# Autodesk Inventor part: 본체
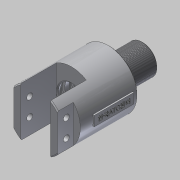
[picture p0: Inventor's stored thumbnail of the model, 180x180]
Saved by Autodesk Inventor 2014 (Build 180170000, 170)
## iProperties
Created: 2019-02
Part Number: 본체
Material: 알루미늄 6061
Document SubType Name: Modeling
Designer: 603-14
Density: 2.71 g/cm^3
Appearance: 알루미늄 - 평지
Mass: 336.883 g
Surface Area: 292.132 cm^2
Volume: 124.311 cm^3
Author: 603-14
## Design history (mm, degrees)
sketch "스케치1"
  geometry: L1 (-36, 0)-(36, 0); L2 (-36, 14)-(-36, 29); L3 (-36, 29)-(2, 29); L4 (2, 29)-(2, 13); L5 (2, 13)-(7, 13); L6 (7, 13)-(7, 15); L7 (7, 15)-(36, 15); L8 (36, 15)-(36, 7); L9 (-36, 14)-(-33.35, 14); L10 (-33.35, 14)-(-33.35, 16.2); L11 (-32.55, 17)-(-29.45, 17); L12 (-28.65, 16.2)-(-28.65, 14); L13 (-28.65, 14)-(-24.35, 14); L14 (-24.35, 14)-(-24.35, 16.2); L15 (-23.55, 17)-(-20.45, 17); L16 (-19.65, 16.2)-(-19.65, 14); L17 (-19.65, 14)-(-16, 14); L18 (-16, 14)-(-16, 17); L19 (-16, 17)-(-9, 17); L20 (-9, 17)-(-9, 4); L21 (-9, 4)-(13, 4); L22 (14, 7)-(36, 7); L23 (-31, 17)-(-31, 19.47); L24 (-22, 17)-(-22, 19.47); L25 (13, 4)-(14, 7); A1 r 0.8 centre (-32.55, 16.2) between (-32.55, 17) and (-33.35, 16.2); A2 r 0.8 centre (-29.45, 16.2) between (-28.65, 16.2) and (-29.45, 17); A3 r 0.8 centre (-23.55, 16.2) between (-23.55, 17) and (-24.35, 16.2); A4 r 0.8 centre (-20.45, 16.2) between (-19.65, 16.2) and (-20.45, 17); 6 further points
  constraints: 50 end point, 13 parallel, 9 perpendicular, 8 point on circle, 8 point on line, 8 tangent, 4 centre point, 3 equal radius, 3 midpoint, 1 coincident, 1 collinear, 1 horizontal
  dimensions: "d1" = 72 distance of L1.start L1.end; "d2" = 5 distance of L4.end L5.end; "d3" = 29 distance of L6.end L7.end; "d4" = 38 distance of L2.end L3.end (derived); "d5" = 58 diameter of L3 L1; "d6" = 30 diameter of L7 L1; "d7" = 26 diameter of L5 L1; "d8" = 27 distance from line of L19.end L2; "d10" = 4.7 distance of point (-33.35, 17) point (-28.65, 17); "d11" = 4.7 distance of point (-24.35, 17) point (-19.65, 17); "d12" = 7 distance of L18.end L19.end; "d15" = 28 diameter of L9 L1; "d16" = 34 diameter of L11 L1; "d17" = 34 diameter of L15 L1; "d18" = 34 diameter of L19 L1 (= d17); "d19" = 28 diameter of L13 L1 (= d15); "d20" = 28 diameter of L17 L1 (= d15); "d21" = 8 diameter of L21 L1; "d23" = 14 diameter of L22 L1; "d24" = 0.8 radius of A1; "d25" = 5 distance between parallel lines of L23 L2; "d26" = 9 distance between parallel lines of L24 L23; "d27" = 22 distance of L8.end L22.start; "d28" = 1 horizontal distance of L22.start L21.end
revolve "회전1" sketch "스케치1" stored, may be unused: angle "d29" = 90 deg
feature "스레드1" dims "d30" = 10, "d31" = 0
chamfer "모따기1" distance "d32" = 1; stored, may be unused: second distance "d33" = 2, angle "d34" = 45 deg
chamfer "모따기2" distance "d35" = 1; stored, may be unused: second distance "d36" = 2, angle "d37" = 45 deg
sketch "스케치2"
  geometry: C1 r 29 at (0, 0) reference; C2 r 15 at (0, 0) reference; 2 further points
  constraints: 1 coincident
extrude "돌출1" join sketch "스케치2" distance "d38" = 36; taper "d39" = 0 deg
sketch "스케치3"
  geometry: L1 (-15, -34.301)-(15, -34.301); L2 (15, -34.301)-(15, 34.301); L3 (15, 34.301)-(-15, 34.301); L4 (-15, 34.301)-(-15, -34.301); L5 (-15, -34.301)-(15, 34.301); L6 (15, -34.301)-(-15, 34.301); 1 further point
  constraints: 12 end point, 2 midpoint, 2 parallel, 1 horizontal, 1 perpendicular
extrude "돌출2" cut sketch "스케치3" distance "d40" = 36; taper "d41" = 0 deg
sketch "스케치4"
  geometry: L1 (22, -18.894)-(22, 18.894); L2 (-22, 18.894)-(-22, -18.894); L3 (-22, -36.828)-(22, 36.828); L4 (22, -36.828)-(-22, 36.828); L5 (15, 24.819)-(15, -24.819) reference; L6 (-15, -24.819)-(-15, 24.819) reference; A1 r 29 centre (0, 0) between (15, -24.819) and (15, 24.819) reference; A2 r 29 centre (0, 0) between (-15, 24.819) and (-15, -24.819) reference; 1 further point
  constraints: 8 end point, 4 point on circle, 2 midpoint, 1 parallel
  dimensions: "d42" = 44 distance between parallel lines of L1 L2
extrude "돌출3" cut sketch "스케치4" distance "d43" = 16; taper "d44" = 0 deg
sketch "스케치5"
  geometry: L1 (0, 0)-(0, 37.789) reference; L2 (16, 0)-(0, 0) reference; L3 (16, 0)-(16, 37.789) reference; L4 (0, 37.789)-(16, 37.789) reference; L5 (0, 0)-(0, 37.789) reference; C1 r 3 at (9, 27.894); C2 r 3 at (9, 9.894); 1 further point
  constraints: 2 centre point, 1 vertical alignment
  dimensions: "d45" = 9 distance from line of C1.centre L1; "d46" = 18 distance of C2.centre C1.centre; "d47" = 6 diameter of C1; "d48" = 6 diameter of C2; "d66" = 9 vertical distance of point (72, 18.894) C1.centre
extrude "돌출4" cut sketch "스케치5" distance "d49" = 56; taper "d50" = 0 deg
chamfer "모따기3" distance "d51" = 1; stored, may be unused: second distance "d52" = 2, angle "d53" = 45 deg
feature "스레드2" dims "d54" = 18, "d55" = 0
node "작업 평면1"
sketch "스케치6"
  geometry: L1 (2, 28)-(2, -28) reference; L2 (-43, -5)-(-3, -5); L3 (-3, -5)-(-3, 5); L4 (-3, 5)-(-43, 5); L5 (-43, 5)-(-43, -5); L6 (-43, -5)-(-3, 5); L7 (-3, -5)-(-43, 5); L8 (0, 0)-(-56.112, 0); L9 (1, -29)-(1, 29) reference; 2 further points
  constraints: 14 end point, 3 midpoint, 2 parallel, 2 perpendicular, 1 horizontal, 1 horizontal alignment
  dimensions: "d57" = 5 distance between parallel lines of L1 L3; "d58" = 40 distance of L3.end L4.end; "d59" = 10 distance of L4.end L2.start
extrude "돌출5" join sketch "스케치6" stored distance "d60" = 56; taper "d61" = 0 deg
sketch "스케치7"
  geometry: L1 (-43, -5)-(-3, -5) reference; L2 (-3, -5)-(-3, 5) reference; L3 (-3, 5)-(-43, 5) reference; L4 (-43, 5)-(-43, -5) reference; 2 further points
  constraints: 1 other
  dimensions: "d62" = 20 distance from line of L4 point (-23, 0); "d63" = 5 distance from line of L1 point (-23, 0)
feature "엠보싱1" sketch "스케치7" dims "d64" = 0.5, "d65" = 0
node "솔리드1"
node "투영된 루프1"
node "투영된 루프2"
node "투영된 루프3"
node "투영된 루프4"
node "투영된 루프5"
